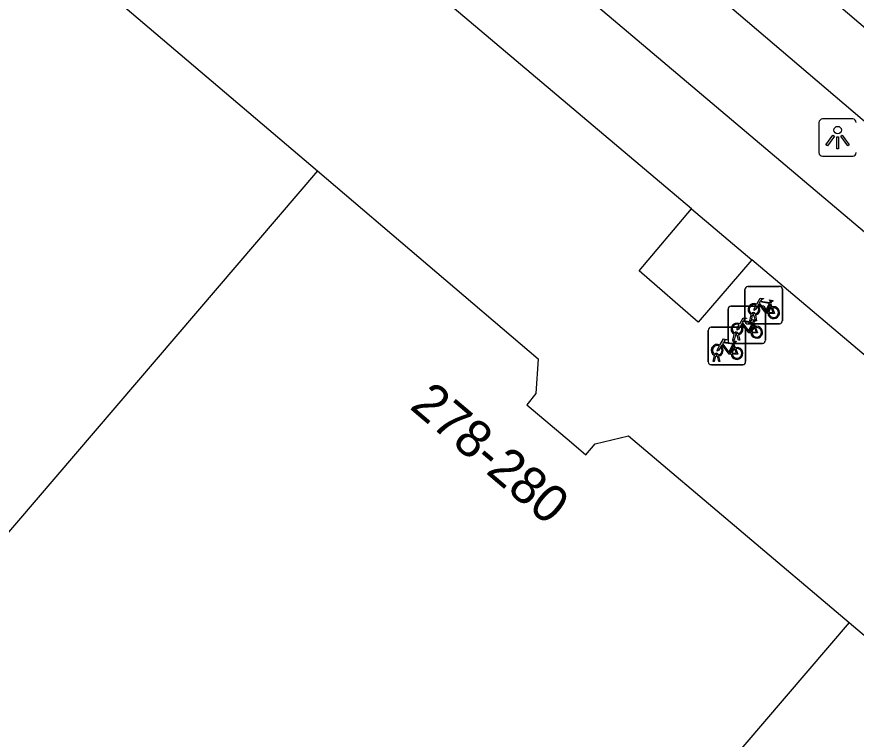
# Model space of a CAD drawing. Extents: x 162347 to 162868, y 381221 to 381813.
# Drawn here: x 162714.57 to 162737.04, y 381609.38 to 381628.72 of the extents above; entities that cross this region are included whole.
import ezdxf

# ---------------------------------------------------------------- set-up
doc = ezdxf.new("R2010")
doc.units = 0
for name, color, linetype in [('IMGEO_Fietsenrek', 7, 'Continuous'), ('IMGEO_Fietspad_gesloten', 7, 'Continuous'), ('IMGEO_Lichtpunt', 7, 'Continuous'), ('IMGEO_Pand', 7, 'Continuous'), ('IMGEO_Pand_nummerreeks', 7, 'Continuous'), ('IMGEO_Parkeervlak_open', 7, 'Continuous'), ('IMGEO_Rijbaan_lokaal_open', 7, 'Continuous'), ('IMGEO_Voetpad_open', 7, 'Continuous')]:
    doc.layers.add(name, color=color, linetype=linetype)

msp = doc.modelspace()

# ---------------------------------------------------------------- linework, layer by layer
at = {"layer": 'IMGEO_Fietsenrek'}
for p, q in [((162734.134, 381621.497), (162734.975, 381621.497)), ((162734.975, 381621.497), (162734.134, 381621.497)), ((162734.059, 381620.572), (162734.059, 381621.413)), ((162734.059, 381621.413), (162734.059, 381620.572)), ((162735.059, 381621.422), (162735.059, 381620.581)), ((162735.059, 381620.581), (162735.059, 381621.422)), ((162734.746, 381621.046), (162734.782, 381620.951)), ((162733.605, 381620.047), (162733.605, 381620.888)), ((162733.605, 381620.888), (162733.605, 381620.047)), ((162733.68, 381620.972), (162734.521, 381620.972)), ((162734.521, 381620.972), (162733.68, 381620.972)), ((162734.605, 381620.897), (162734.605, 381620.056)), ((162734.605, 381620.056), (162734.605, 381620.897)), ((162734.186, 381620.581), (162734.225, 381620.741)), ((162734.255, 381620.729), (162734.22, 381620.581)), ((162734.297, 381620.753), (162734.296, 381620.757)), ((162734.338, 381620.581), (162734.304, 381620.723)), ((162734.328, 381620.764), (162734.329, 381620.757)), ((162734.336, 381620.727), (162734.371, 381620.581)), ((162733.151, 381620.404), (162733.992, 381620.404)), ((162733.992, 381620.404), (162733.151, 381620.404)), ((162734.984, 381620.497), (162734.143, 381620.497)), ((162734.143, 381620.497), (162734.984, 381620.497)), ((162734.22, 381620.581), (162734.186, 381620.581)), ((162734.292, 381620.521), (162734.328, 381620.426)), ((162734.371, 381620.581), (162734.338, 381620.581)), ((162733.076, 381619.479), (162733.076, 381620.32)), ((162733.076, 381620.32), (162733.076, 381619.479)), ((162733.732, 381620.056), (162733.771, 381620.216)), ((162733.801, 381620.204), (162733.766, 381620.056)), ((162733.843, 381620.228), (162733.842, 381620.232)), ((162733.884, 381620.056), (162733.85, 381620.198)), ((162733.874, 381620.239), (162733.875, 381620.232)), ((162733.882, 381620.202), (162733.917, 381620.056)), ((162734.076, 381620.329), (162734.076, 381619.488)), ((162734.076, 381619.488), (162734.076, 381620.329)), ((162734.53, 381619.972), (162733.689, 381619.972)), ((162733.689, 381619.972), (162734.53, 381619.972)), ((162733.766, 381620.056), (162733.732, 381620.056)), ((162733.763, 381619.953), (162733.799, 381619.858)), ((162733.917, 381620.056), (162733.884, 381620.056)), ((162733.203, 381619.488), (162733.242, 381619.648)), ((162733.237, 381619.488), (162733.203, 381619.488)), ((162733.272, 381619.636), (162733.237, 381619.488)), ((162733.314, 381619.66), (162733.313, 381619.664)), ((162733.355, 381619.488), (162733.321, 381619.63)), ((162733.345, 381619.671), (162733.346, 381619.664)), ((162733.353, 381619.634), (162733.388, 381619.488)), ((162733.388, 381619.488), (162733.355, 381619.488)), ((162734.001, 381619.404), (162733.16, 381619.404)), ((162733.16, 381619.404), (162734.001, 381619.404))]:
    msp.add_line(p, q, dxfattribs=at)
for points in [[(162734.372, 381621.023), (162734.467, 381621.187), (162734.553, 381621.173), (162734.555, 381621.164), (162734.499, 381621.153), (162734.472, 381621.108), (162734.728, 381621.067)], [(162734.715, 381621.042), (162734.458, 381621.083), (162734.441, 381621.054), (162734.608, 381620.834), (162734.715, 381621.042)], [(162734.728, 381621.067), (162734.753, 381621.116), (162734.747, 381621.12), (162734.724, 381621.124), (162734.712, 381621.131), (162734.711, 381621.134), (162734.713, 381621.139), (162734.808, 381621.124), (162734.81, 381621.114), (162734.8, 381621.101), (162734.788, 381621.095), (162734.774, 381621.101), (162734.746, 381621.046)], [(162734.393, 381620.971), (162734.341, 381620.881), (162734.301, 381620.856), (162734.302, 381620.903), (162734.357, 381620.997)], [(162734.668, 381620.779), (162734.618, 381620.779), (162734.427, 381621.03), (162734.408, 381620.998)], [(162734.763, 381620.944), (162734.733, 381621.021), (162734.624, 381620.803), (162734.667, 381620.803)], [(162734.697, 381620.803), (162734.817, 381620.802), (162734.773, 381620.916)], [(162734.793, 381620.923), (162734.848, 381620.778), (162734.698, 381620.778)], [(162733.918, 381620.498), (162734.013, 381620.662), (162734.099, 381620.648), (162734.101, 381620.639), (162734.045, 381620.628), (162734.018, 381620.583), (162734.274, 381620.542)], [(162734.274, 381620.542), (162734.299, 381620.591), (162734.293, 381620.595), (162734.27, 381620.599), (162734.258, 381620.606), (162734.257, 381620.609), (162734.259, 381620.614), (162734.354, 381620.599), (162734.356, 381620.589), (162734.346, 381620.576), (162734.334, 381620.57), (162734.32, 381620.576), (162734.292, 381620.521)], [(162733.939, 381620.446), (162733.887, 381620.356), (162733.847, 381620.331), (162733.848, 381620.378), (162733.903, 381620.472)], [(162734.214, 381620.254), (162734.164, 381620.254), (162733.973, 381620.505), (162733.954, 381620.473)], [(162734.261, 381620.517), (162734.004, 381620.558), (162733.987, 381620.529), (162734.154, 381620.309), (162734.261, 381620.517)], [(162734.309, 381620.419), (162734.279, 381620.496), (162734.17, 381620.278), (162734.213, 381620.278)], [(162734.243, 381620.278), (162734.363, 381620.277), (162734.319, 381620.391)], [(162734.339, 381620.398), (162734.394, 381620.253), (162734.244, 381620.253)], [(162733.389, 381619.93), (162733.484, 381620.094), (162733.57, 381620.08), (162733.572, 381620.071), (162733.516, 381620.06), (162733.489, 381620.015), (162733.745, 381619.974)], [(162733.685, 381619.686), (162733.635, 381619.686), (162733.444, 381619.937), (162733.425, 381619.905)], [(162733.732, 381619.949), (162733.475, 381619.99), (162733.458, 381619.961), (162733.625, 381619.741), (162733.732, 381619.949)], [(162733.78, 381619.851), (162733.75, 381619.928), (162733.641, 381619.71), (162733.684, 381619.71)], [(162733.745, 381619.974), (162733.77, 381620.023), (162733.764, 381620.027), (162733.741, 381620.031), (162733.729, 381620.038), (162733.728, 381620.041), (162733.73, 381620.046), (162733.825, 381620.031), (162733.827, 381620.021), (162733.817, 381620.008), (162733.805, 381620.002), (162733.791, 381620.008), (162733.763, 381619.953)], [(162733.41, 381619.878), (162733.358, 381619.788), (162733.318, 381619.763), (162733.319, 381619.81), (162733.374, 381619.904)], [(162733.714, 381619.71), (162733.834, 381619.709), (162733.79, 381619.823)], [(162733.81, 381619.83), (162733.865, 381619.685), (162733.715, 381619.685)]]:
    msp.add_lwpolyline(points, dxfattribs=at)
for centre, radius, start, end in [((162734.137, 381621.419), 0.0779, 92.4484, 184.2845), ((162734.137, 381621.419), 0.0779, 92.4484, 184.2845), ((162734.981, 381621.419), 0.0779, 2.4484, 94.2845), ((162734.981, 381621.419), 0.0779, 2.4484, 94.2845), ((162734.299, 381620.882), 0.159, 62.6766, 242.1369), ((162733.683, 381620.894), 0.0779, 92.4484, 184.2845), ((162733.683, 381620.894), 0.0779, 92.4484, 184.2845), ((162734.299, 381620.882), 0.129, 63.3192, 238.903), ((162734.299, 381620.882), 0.129, 283.6043, 43.4302), ((162734.299, 381620.882), 0.159, 283.5766, 46.6042), ((162734.527, 381620.894), 0.0779, 2.4484, 94.2845), ((162734.527, 381620.894), 0.0779, 2.4484, 94.2845), ((162734.826, 381620.798), 0.159, 113.3408, 178.3217), ((162734.826, 381620.798), 0.159, 187.0065, 105.7708), ((162734.826, 381620.798), 0.129, 113.923, 177.9556), ((162734.826, 381620.798), 0.129, 188.6715, 104.5883), ((162734.279, 381620.753), 0.0499, 12.8025, 158.6934), ((162734.299, 381620.882), 0.159, 253.9967, 271.7867), ((162734.279, 381620.753), 0.0174, 12.8025, 163.4502), ((162734.299, 381620.882), 0.129, 253.415, 269.0204), ((162733.154, 381620.326), 0.0779, 92.4484, 184.2845), ((162733.154, 381620.326), 0.0779, 92.4484, 184.2845), ((162733.845, 381620.357), 0.159, 62.6766, 242.1369), ((162733.845, 381620.357), 0.129, 63.3192, 238.903), ((162733.845, 381620.357), 0.129, 283.6043, 43.4302), ((162733.845, 381620.357), 0.159, 283.5766, 46.6042), ((162733.998, 381620.326), 0.0779, 2.4484, 94.2845), ((162733.998, 381620.326), 0.0779, 2.4484, 94.2845), ((162734.137, 381620.575), 0.0779, 182.4484, 274.2845), ((162734.137, 381620.575), 0.0779, 182.4484, 274.2845), ((162734.372, 381620.273), 0.159, 113.3408, 178.3217), ((162734.372, 381620.273), 0.159, 187.0065, 105.7708), ((162734.372, 381620.273), 0.129, 113.923, 177.9556), ((162734.372, 381620.273), 0.129, 188.6715, 104.5883), ((162734.981, 381620.575), 0.0779, 272.4484, 4.2845), ((162734.981, 381620.575), 0.0779, 272.4484, 4.2845), ((162733.825, 381620.228), 0.0499, 12.8025, 158.6934), ((162733.845, 381620.357), 0.159, 253.9967, 271.7867), ((162733.825, 381620.228), 0.0174, 12.8025, 163.4502), ((162733.845, 381620.357), 0.129, 253.415, 269.0204), ((162733.316, 381619.789), 0.159, 62.6766, 242.1369), ((162733.316, 381619.789), 0.129, 63.3192, 238.903), ((162733.683, 381620.05), 0.0779, 182.4484, 274.2845), ((162733.683, 381620.05), 0.0779, 182.4484, 274.2845), ((162734.527, 381620.05), 0.0779, 272.4484, 4.2845), ((162734.527, 381620.05), 0.0779, 272.4484, 4.2845), ((162733.296, 381619.66), 0.0499, 12.8025, 158.6934), ((162733.316, 381619.789), 0.129, 283.6043, 43.4302), ((162733.316, 381619.789), 0.159, 283.5766, 46.6042), ((162733.843, 381619.705), 0.159, 113.3408, 178.3217), ((162733.843, 381619.705), 0.159, 187.0065, 105.7708), ((162733.843, 381619.705), 0.129, 113.923, 177.9556), ((162733.843, 381619.705), 0.129, 188.6715, 104.5883), ((162733.154, 381619.482), 0.0779, 182.4484, 274.2845), ((162733.154, 381619.482), 0.0779, 182.4484, 274.2845), ((162733.316, 381619.789), 0.159, 253.9967, 271.7867), ((162733.296, 381619.66), 0.0174, 12.8025, 163.4502), ((162733.316, 381619.789), 0.129, 253.415, 269.0204), ((162733.998, 381619.482), 0.0779, 272.4484, 4.2845), ((162733.998, 381619.482), 0.0779, 272.4484, 4.2845)]:
    msp.add_arc(centre, radius, start, end, dxfattribs=at)
at = {"layer": 'IMGEO_Fietspad_gesloten'}
for points in [[(162722.898, 381635.101), (162740.536, 381620.194)], [(162732.624, 381623.574), (162720.034, 381634.212)], [(162732.624, 381623.574), (162734.239, 381622.209)], [(162746.831, 381611.57), (162743.076, 381614.743), (162734.239, 381622.209)]]:
    msp.add_lwpolyline(points, dxfattribs=at)
at = {"layer": 'IMGEO_Lichtpunt'}
for p, q in [((162736.942, 381625.983), (162736.134, 381625.983)), ((162736.942, 381625.983), (162736.134, 381625.983)), ((162736.04, 381625.888), (162736.04, 381625.081)), ((162736.04, 381625.888), (162736.04, 381625.081)), ((162736.134, 381624.987), (162736.942, 381624.987)), ((162736.134, 381624.987), (162736.942, 381624.987))]:
    msp.add_line(p, q, dxfattribs=at)
for points in [[(162736.414, 381625.552), (162736.453, 381625.524), (162736.265, 381625.262), (162736.227, 381625.289), (162736.414, 381625.552)], [(162736.626, 381625.524), (162736.664, 381625.551), (162736.851, 381625.289), (162736.812, 381625.261), (162736.626, 381625.524)], [(162736.516, 381625.504), (162736.563, 381625.504), (162736.563, 381625.182), (162736.516, 381625.182), (162736.516, 381625.504)]]:
    msp.add_lwpolyline(points, dxfattribs=at)
msp.add_circle((162736.539, 381625.686), 0.0994, dxfattribs=at)
for centre, start, end in [((162736.134, 381625.888), 90, 180), ((162736.134, 381625.888), 90, 180), ((162736.942, 381625.888), 0, 90), ((162736.942, 381625.888), 0, 90), ((162736.134, 381625.081), 180, 270), ((162736.134, 381625.081), 180, 270), ((162736.942, 381625.081), 270, 0), ((162736.942, 381625.081), 270, 360)]:
    msp.add_arc(centre, 0.0946, start, end, dxfattribs=at)
at = {"layer": 'IMGEO_Pand'}
for points in [[(162708.391, 381636.674), (162714.347, 381631.615), (162714.245, 381630.614), (162714.036, 381630.358), (162715.605, 381629.033), (162715.798, 381629.263), (162716.804, 381629.538), (162722.614, 381624.591)], [(162722.614, 381624.591), (162711.285, 381611.345)], [(162722.614, 381624.591), (162728.523, 381619.56), (162728.46, 381618.633), (162728.221, 381618.325), (162728.841, 381617.803), (162729.413, 381617.32), (162729.803, 381616.992), (162730.049, 381617.281), (162730.942, 381617.502), (162736.849, 381612.501)], [(162736.849, 381612.501), (162725.513, 381599.243)], [(162736.849, 381612.501), (162742.724, 381607.528), (162742.611, 381606.552), (162742.402, 381606.301), (162743.961, 381604.974), (162744.187, 381605.228), (162745.129, 381605.46), (162750.894, 381600.568)]]:
    msp.add_lwpolyline(points, dxfattribs=at)
at = {"layer": 'IMGEO_Parkeervlak_open'}
msp.add_lwpolyline([(162754.407, 381613.79), (162753.144, 381612.386), (162716.734, 381643.412), (162718.101, 381644.792)], dxfattribs=at)
at = {"layer": 'IMGEO_Rijbaan_lokaal_open'}
msp.add_lwpolyline([(162754.407, 381613.79), (162718.101, 381644.792)], dxfattribs=at)
at = {"layer": 'IMGEO_Voetpad_open'}
msp.add_lwpolyline([(162734.239, 381622.209), (162732.804, 381620.54), (162731.227, 381621.914), (162732.624, 381623.574)], dxfattribs=at)

# ---------------------------------------------------------------- texts
at = {"layer": 'IMGEO_Pand_nummerreeks'}
msp.add_text('278-280', height=1, rotation=319.6924, dxfattribs=at).set_placement((162725.053, 381618.249))

doc.saveas('drawing.dxf')
